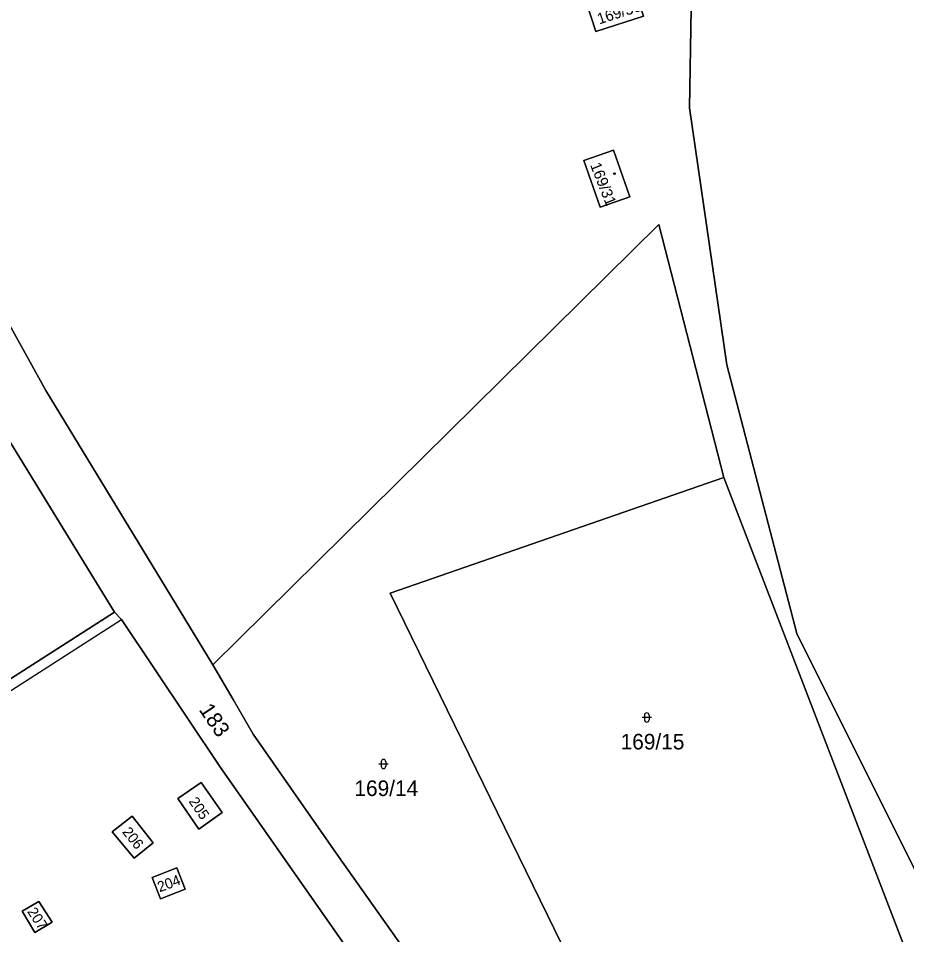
# Model space of a CAD drawing. Extents: x -600309 to -598967, y -1161267 to -1160292.
# Drawn here: x -599299.8 to -599203, y -1160880.6 to -1160780.7 of the extents above; entities that cross this region are included whole.
import ezdxf

# ---------------------------------------------------------------- set-up
doc = ezdxf.new("R2010")
doc.units = 0
for name, color, linetype in [('Level 1', 7, 'Continuous'), ('Level 3', 7, 'Continuous'), ('Level 4', 7, 'Continuous'), ('Level 5', 7, 'Continuous'), ('Level 60', 7, 'Continuous')]:
    doc.layers.add(name, color=color, linetype=linetype)

msp = doc.modelspace()

# ---------------------------------------------------------------- linework, layer by layer
at = {"layer": 'Level 1'}
for points in [[(-599186.14, -1160884.73), (-599187.69, -1160881.34), (-599196.93, -1160883.84), (-599214.95, -1160847.74), (-599222.56, -1160818.46), (-599226.63, -1160790.42), (-599226.46, -1160779.61), (-599224.76, -1160776.46), (-599213.89, -1160771.2), (-599202.26, -1160766.2), (-599191.88, -1160764.74), (-599191.33, -1160772.76), (-599189.43, -1160772.06)], [(-599237.9, -1160778.88), (-599236.85, -1160782.11), (-599231.67, -1160780.44), (-599232.74, -1160777.21)], [(-599238.15, -1160796.16), (-599234.94, -1160795.03), (-599233.16, -1160800.13), (-599236.37, -1160801.25), (-599238.15, -1160796.16)], [(-599308.94, -1160799.38), (-599296.81, -1160821.25), (-599278.59, -1160851.16)], [(-599289.31, -1160845.42), (-599302.32, -1160824.26), (-599313.63, -1160801.54)], [(-599278.59, -1160851.16), (-599230, -1160803.14), (-599222.91, -1160830.72)], [(-599222.91, -1160830.72), (-599259.27, -1160843.35), (-599235.9, -1160891.19), (-599214.32, -1160887.67)], [(-599222.91, -1160830.72), (-599203.12, -1160882.13), (-599214.32, -1160887.67)], [(-599341.16, -1160878.63), (-599289.31, -1160845.42)], [(-599289.31, -1160845.42), (-599288.57, -1160846.23)], [(-599288.57, -1160846.23), (-599277.78, -1160862.37), (-599260.53, -1160886.96)], [(-599278.59, -1160851.16), (-599276.4, -1160854.93), (-599274.2, -1160858.73), (-599264.9, -1160872.08), (-599253.75, -1160887.85)], [(-599282.41, -1160865.74), (-599279.89, -1160863.99), (-599277.59, -1160867.28), (-599280.14, -1160869.07), (-599282.41, -1160865.74)], [(-599289.56, -1160869.39), (-599287.41, -1160867.68), (-599285.11, -1160870.58), (-599287.19, -1160872.23), (-599289.56, -1160869.39)], [(-599285.22, -1160874.36), (-599282.53, -1160873.29), (-599281.61, -1160875.61), (-599284.31, -1160876.68), (-599285.22, -1160874.36)], [(-599299.39, -1160878.04), (-599297.56, -1160876.97), (-599296.12, -1160879.24), (-599298.01, -1160880.36), (-599299.39, -1160878.04)]]:
    msp.add_lwpolyline(points, dxfattribs=at)
at = {"layer": 'Level 3'}
msp.add_lwpolyline([(-599341.01, -1160879.91), (-599288.57, -1160846.23)], dxfattribs=at)
at = {"layer": 'Level 5'}
for p, q in [((-599231.3, -1160856.9), (-599231.8, -1160856.9)), ((-599231.55, -1160856.65), (-599231.55, -1160857.15)), ((-599230.8, -1160856.9), (-599231.3, -1160856.9)), ((-599231.05, -1160856.65), (-599231.05, -1160857.15)), ((-599260, -1160861.98), (-599260.5, -1160861.98)), ((-599260.25, -1160861.73), (-599260.25, -1160862.23)), ((-599259.5, -1160861.98), (-599260, -1160861.98)), ((-599259.75, -1160861.73), (-599259.75, -1160862.23))]:
    msp.add_line(p, q, dxfattribs=at)
for radius in [0.09, 0.0521]:
    msp.add_circle((-599234.82, -1160797.6), radius, dxfattribs=at)
for centre, start, end in [((-599231.3, -1160856.65), 0, 180), ((-599231.3, -1160857.15), 180, 0), ((-599260, -1160861.73), 0, 180), ((-599260, -1160862.23), 180, 0)]:
    msp.add_arc(centre, 0.25, start, end, dxfattribs=at)
at = {"layer": 'Level 60'}
for points in [[(-599189.43, -1160772.06), (-599179.89, -1160797.48), (-599173.47, -1160813.83), (-599164.5, -1160836.42), (-599142.41, -1160891.59), (-599155.79, -1160894.66), (-599159.17, -1160885.23), (-599160.28, -1160881.49), (-599161.27, -1160878.6), (-599179.49, -1160880.56), (-599186.14, -1160884.73), (-599187.69, -1160881.34), (-599196.93, -1160883.84), (-599214.95, -1160847.74), (-599222.56, -1160818.46), (-599226.63, -1160790.42), (-599226.46, -1160779.61), (-599224.76, -1160776.46), (-599213.89, -1160771.2), (-599202.26, -1160766.2), (-599191.88, -1160764.74), (-599191.33, -1160772.76)], [(-599233.77, -1160774.05), (-599238.93, -1160775.71), (-599237.9, -1160778.88), (-599236.85, -1160782.11), (-599231.67, -1160780.44), (-599232.74, -1160777.21)], [(-599237.9, -1160778.88), (-599232.74, -1160777.21), (-599231.67, -1160780.44), (-599236.85, -1160782.11)], [(-599234.94, -1160795.03), (-599238.15, -1160796.16), (-599236.37, -1160801.25), (-599233.16, -1160800.13)], [(-599238.15, -1160796.16), (-599234.94, -1160795.03), (-599233.16, -1160800.13), (-599236.37, -1160801.25)], [(-599289.31, -1160845.42), (-599341.16, -1160878.63), (-599343.28, -1160852.34), (-599343.45, -1160850.23), (-599343.88, -1160844.93), (-599344.2, -1160823.41), (-599344.18, -1160821.01), (-599344.19, -1160819.67), (-599314.23, -1160800.67), (-599313.63, -1160801.54), (-599302.32, -1160824.26)], [(-599264.9, -1160872.08), (-599274.2, -1160858.73), (-599276.4, -1160854.93), (-599278.59, -1160851.16), (-599230, -1160803.14), (-599222.91, -1160830.72), (-599259.27, -1160843.35), (-599235.9, -1160891.19), (-599214.32, -1160887.67), (-599237.8, -1160901.47), (-599252.6, -1160887.12), (-599253.75, -1160887.85)], [(-599259.27, -1160843.35), (-599222.91, -1160830.72), (-599203.12, -1160882.13), (-599214.32, -1160887.67), (-599235.9, -1160891.19)], [(-599339.6, -1160898.84), (-599341.01, -1160879.91), (-599341.16, -1160878.63), (-599289.31, -1160845.42), (-599288.57, -1160846.23), (-599277.78, -1160862.37), (-599260.53, -1160886.96), (-599315.39, -1160922.67), (-599314.84, -1160923.85), (-599313.86, -1160925.94), (-599321.48, -1160914.61), (-599328.73, -1160906.84), (-599336.91, -1160900.39)], [(-599279.89, -1160863.99), (-599282.41, -1160865.74), (-599280.14, -1160869.07), (-599277.59, -1160867.28)], [(-599282.41, -1160865.74), (-599279.89, -1160863.99), (-599277.59, -1160867.28), (-599280.14, -1160869.07)], [(-599287.41, -1160867.68), (-599289.56, -1160869.39), (-599287.19, -1160872.23), (-599285.11, -1160870.58)], [(-599289.56, -1160869.39), (-599287.41, -1160867.68), (-599285.11, -1160870.58), (-599287.19, -1160872.23)], [(-599282.53, -1160873.29), (-599285.22, -1160874.36), (-599284.31, -1160876.68), (-599281.61, -1160875.61)], [(-599285.22, -1160874.36), (-599282.53, -1160873.29), (-599281.61, -1160875.61), (-599284.31, -1160876.68)], [(-599297.56, -1160876.97), (-599299.39, -1160878.04), (-599298.01, -1160880.36), (-599296.12, -1160879.24)], [(-599299.39, -1160878.04), (-599297.56, -1160876.97), (-599296.12, -1160879.24), (-599298.01, -1160880.36)]]:
    msp.add_lwpolyline(points, close=True, dxfattribs=at)
for points in [[(-599226.46, -1160779.61), (-599226.63, -1160790.42), (-599222.56, -1160818.46), (-599214.95, -1160847.74), (-599196.93, -1160883.84), (-599187.69, -1160881.34), (-599186.14, -1160884.73), (-599185.42, -1160887.84), (-599179.59, -1160887.16), (-599179.57, -1160890), (-599192, -1160891.53), (-599193.25, -1160886.06), (-599201.97, -1160883.95), (-599210.91, -1160887.57), (-599214.32, -1160887.67), (-599203.12, -1160882.13), (-599222.91, -1160830.72), (-599230, -1160803.14), (-599278.59, -1160851.16), (-599296.81, -1160821.25), (-599308.94, -1160799.38)], [(-599308.94, -1160799.38), (-599296.81, -1160821.25), (-599278.59, -1160851.16), (-599276.4, -1160854.93), (-599274.2, -1160858.73), (-599264.9, -1160872.08), (-599253.75, -1160887.85), (-599235.72, -1160913.36), (-599296.6, -1160957.23), (-599301.64, -1160965.46)], [(-599300.33, -1160954.93), (-599298.11, -1160953.25), (-599273.84, -1160935.22), (-599248.33, -1160916.3), (-599247.27, -1160915.32), (-599245.94, -1160914.13), (-599245.11, -1160912.69), (-599244.95, -1160911.26), (-599245.44, -1160907.97), (-599259.93, -1160887.85), (-599260.53, -1160886.96), (-599277.78, -1160862.37), (-599288.57, -1160846.23), (-599289.31, -1160845.42), (-599302.32, -1160824.26)]]:
    msp.add_lwpolyline(points, dxfattribs=at)

# ---------------------------------------------------------------- texts
at = {"layer": 'Level 4'}
for s, height, rotation, p in [('169/36', 1.2, 18, (-599236.48, -1160781.34)), ('169/31', 1.2, 291.6, (-599237.49, -1160796.66)), ('183', 1.7, 304.2, (-599280.17, -1160856.07)), ('205', 1.14, 303.99651, (-599281.271, -1160866.055)), ('206', 1.14, 308.58921, (-599288.534, -1160869.405)), ('204', 1.14, 20.64699, (-599284.391, -1160875.976)), ('207', 1.14, 303.34077, (-599298.881, -1160878.07))]:
    msp.add_text(s, height=height, rotation=rotation, dxfattribs=at).set_placement(p)
for s, p in [('169/15', (-599234.15, -1160860.39)), ('169/14', (-599263.17, -1160865.47))]:
    msp.add_text(s, height=1.7, dxfattribs=at).set_placement(p)

doc.saveas('drawing.dxf')
